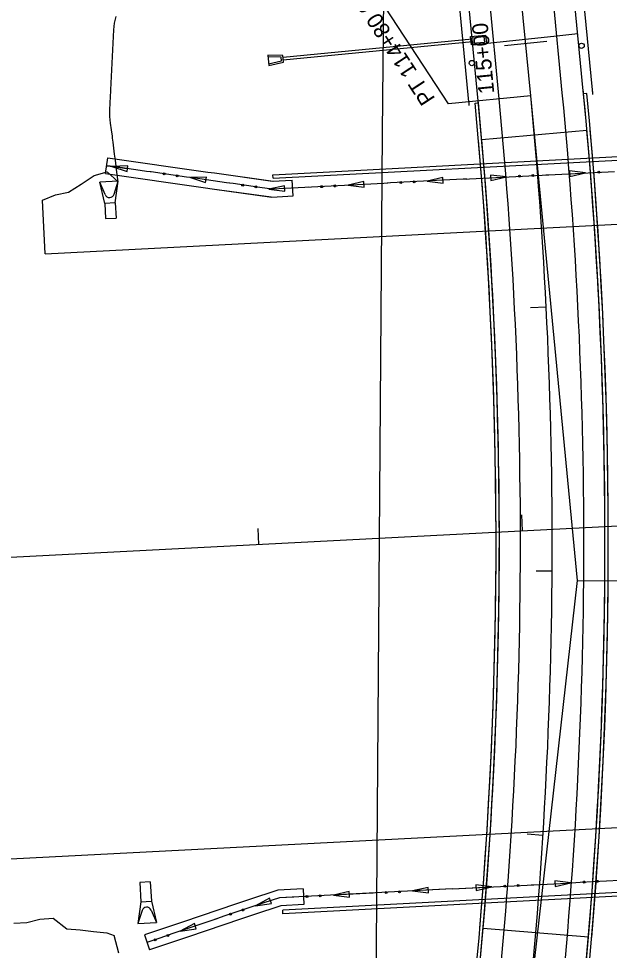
# Model space of a CAD drawing. Extents: x 1311167 to 1314552, y 2087587 to 2090602.
# Drawn here: x 1313861.6 to 1314085.4, y 2089153.5 to 2089506 of the extents above; entities that cross this region are included whole.
import ezdxf

# ---------------------------------------------------------------- set-up
doc = ezdxf.new("R2010")
doc.units = 0
for name, color, linetype in [('MOT_Proposed Road_1A', 7, 'Continuous'), ('MOT_Proposed Road_2', 7, 'Continuous'), ('R_Bridge', 7, 'Continuous'), ('R_Guardrail', 7, 'Continuous'), ('R_Horz Alg Annot_Side Road', 7, 'Continuous'), ('R_Horz Alg Stationing', 7, 'Continuous'), ('R_Proposed Road', 7, 'Continuous'), ('R_Shoulder', 7, 'Continuous'), ('R_Special Ditch', 7, 'Continuous'), ('S_DITCHLINE', 7, 'Continuous'), ('S_EDGE_BITUMINOUS', 7, 'Continuous'), ('S_EDGE_CONCRETE', 7, 'Continuous'), ('S_EDGE_PAVEMENT', 7, 'Continuous'), ('S_PAVEMENT_CROWN', 7, 'Continuous'), ('S_WALL', 7, 'Continuous')]:
    doc.layers.add(name, color=color, linetype=linetype)

msp = doc.modelspace()

# ---------------------------------------------------------------- linework, layer by layer
at = {"layer": 'MOT_Proposed Road_1A'}
for p, q in [((1313894.56, 2089447.41), (1313895.4, 2089453.35)), ((1313957.76, 2089444.53), (1313965.27, 2089444.92)), ((1313965.59, 2089438.93), (1313965.27, 2089444.92)), ((1313957.5, 2089438.51), (1313965.59, 2089438.93)), ((1313969.36, 2089176.77), (1313969.68, 2089170.78)), ((1313909.25, 2089159.3), (1313911.18, 2089153.61))]:
    msp.add_line(p, q, dxfattribs=at)
for points in [[(1313895.4, 2089453.35), (1313933.23, 2089447.99), (1313935.75, 2089447.64), (1313957.76, 2089444.53)], [(1313895.4, 2089453.35), (1313933.23, 2089447.99), (1313935.75, 2089447.64), (1313958.05, 2089444.49)], [(1313894.56, 2089447.41), (1313932.39, 2089442.05), (1313934.91, 2089441.69), (1313957.5, 2089438.51)], [(1313894.56, 2089447.41), (1313932.39, 2089442.05), (1313934.91, 2089441.69), (1313957.21, 2089438.55)], [(1313969.36, 2089176.77), (1313959.83, 2089176.28), (1313948.64, 2089172.62), (1313943.7, 2089170.97), (1313924.01, 2089164.29), (1313919.09, 2089162.62), (1313909.25, 2089159.3)], [(1313969.68, 2089170.78), (1313960.94, 2089170.33), (1313950.52, 2089166.92), (1313945.61, 2089165.28), (1313925.94, 2089158.61), (1313921.02, 2089156.94), (1313911.18, 2089153.61)]]:
    msp.add_lwpolyline(points, dxfattribs=at)
at = {"layer": 'MOT_Proposed Road_2'}
for p, q in [((1314075.48, 2089478.75), (1314071.45, 2089520.56)), ((1314035.66, 2089474.91), (1314031.6, 2089517.08))]:
    msp.add_line(p, q, dxfattribs=at)
for centre in [(1314074.84, 2089495.76), (1314033.28, 2089489.21)]:
    msp.add_circle(centre, 1, dxfattribs=at)
for radius, start in [(1782.95, 5.44344), (1742.95, 5.45487)]:
    msp.add_arc((1312300.74, 2089307.86), radius, start, 5.5, dxfattribs=at)
at = {"layer": 'R_Bridge'}
for points in [[(1314045.69, 2089495.92), (1314061.62, 2089497.45)], [(1314055.44, 2089396.7), (1314061.43, 2089397)], [(1314057.65, 2089297.08), (1314063.65, 2089297.04)], [(1314054.21, 2089197.49), (1314060.2, 2089197.11)]]:
    msp.add_lwpolyline(points, dxfattribs=at)
at = {"layer": 'R_Guardrail'}
msp.add_line((1314024.38, 2089473.82), (1313981.59, 2089539.33), dxfattribs=at)
for points in [[(1314055.57, 2089476.83), (1314024.38, 2089473.82)], [(1314052.57, 2089110.2), (1314073.23, 2089293.36), (1314055.57, 2089476.83)], [(1314073.23, 2089293.36), (1314193.23, 2089292.37)]]:
    msp.add_lwpolyline(points, dxfattribs=at)
at = {"layer": 'R_Horz Alg Annot_Side Road'}
for p, q in [((1314078.96, 2089479.08), (1314074.93, 2089520.9)), ((1314032.18, 2089474.58), (1314028.12, 2089516.74))]:
    msp.add_line(p, q, dxfattribs=at)
for radius, start in [(1786.45, 5.44344), (1739.45, 5.45487)]:
    msp.add_arc((1312300.74, 2089307.86), radius, start, 5.5, dxfattribs=at)
at = {"layer": 'R_Horz Alg Stationing'}
for p, q in [((1313999.49, 2089462.84), (1314005.79, 2090288.55)), ((1313997.14, 2089155.24), (1313999.49, 2089462.84)), ((1313988.32, 2088000.7), (1313997.14, 2089155.24))]:
    msp.add_line(p, q, dxfattribs=at)
at = {"layer": 'R_Proposed Road'}
for p, q in [((1314055.57, 2089476.83), (1314011.87, 2089930.69)), ((1314055.57, 2089476.83), (1314011.87, 2089930.69)), ((1313503.08, 2089283.78), (1314551.67, 2089338.12))]:
    msp.add_line(p, q, dxfattribs=at)
msp.add_arc((1312300.74, 2089307.86), 1762.95, 353.5625, 5.5, dxfattribs=at)
msp.add_arc((1312300.74, 2089307.86), 1762.95, 353.5625, 5.5, dxfattribs=at)
at = {"layer": 'R_Shoulder'}
for points in [[(1314052.03, 2089318.24), (1314052.34, 2089312.25)], [(1313952.17, 2089313.06), (1313952.48, 2089307.07)]]:
    msp.add_lwpolyline(points, dxfattribs=at)
at = {"layer": 'R_Special Ditch'}
for p, q in [((1314076.83, 2089477.72), (1314075.59, 2089477.6)), ((1314034.49, 2089474.01), (1314035.74, 2089474.13)), ((1314076.86, 2089463.66), (1314037.01, 2089460.19)), ((1314077.41, 2089158.47), (1314037.55, 2089161.79))]:
    msp.add_line(p, q, dxfattribs=at)
for radius, start, end in [(1782.95, 354.7437, 5.46314), (1784.2, 354.74371, 5.46313), (1742.95, 354.73258, 5.47426), (1741.7, 354.73258, 5.47425), (1782.95, 355.19361, 5.01323), (1784.2, 355.19363, 5.01321), (1741.7, 355.19278, 5.01406), (1742.95, 355.19281, 5.01403)]:
    msp.add_arc((1312300.74, 2089307.86), radius, start, end, dxfattribs=at)
at = {"layer": 'S_DITCHLINE'}
for p, q in [((1313903.01, 2089450.31), (1313896.92, 2089450.11)), ((1313896.92, 2089450.11), (1313902.71, 2089448.22)), ((1313902.71, 2089448.22), (1313903.01, 2089450.31)), ((1313932.75, 2089446.1), (1313926.66, 2089445.89)), ((1313926.66, 2089445.89), (1313932.45, 2089444)), ((1313932.45, 2089444), (1313932.75, 2089446.1)), ((1314022.32, 2089445.93), (1314016.39, 2089444.56)), ((1314022.43, 2089443.82), (1314022.32, 2089445.93)), ((1314046.35, 2089446.12), (1314040.3, 2089446.86)), ((1314040.3, 2089446.86), (1314040.41, 2089444.75)), ((1314046.35, 2089446.12), (1314040.3, 2089446.86)), ((1314040.3, 2089446.86), (1314040.41, 2089444.75)), ((1314040.41, 2089444.75), (1314046.35, 2089446.12)), ((1314040.41, 2089444.75), (1314046.35, 2089446.12)), ((1314076.34, 2089447.67), (1314070.3, 2089448.42)), ((1314070.3, 2089448.42), (1314070.41, 2089446.3)), ((1314076.34, 2089447.67), (1314070.3, 2089448.42)), ((1314070.3, 2089448.42), (1314070.41, 2089446.3)), ((1314070.41, 2089446.3), (1314076.34, 2089447.67)), ((1314070.41, 2089446.3), (1314076.34, 2089447.67)), ((1313962.33, 2089442.82), (1313956.39, 2089441.45)), ((1313962.44, 2089440.71), (1313962.33, 2089442.82)), ((1313992.33, 2089444.38), (1313986.39, 2089443.01)), ((1313986.39, 2089443.01), (1313992.44, 2089442.26)), ((1313992.44, 2089442.26), (1313992.33, 2089444.38)), ((1314016.39, 2089444.56), (1314022.43, 2089443.82)), ((1313956.39, 2089441.45), (1313962.44, 2089440.71)), ((1314040.8, 2089177.47), (1314034.76, 2089178.22)), ((1314034.76, 2089178.22), (1314034.86, 2089176.1)), ((1314070.8, 2089179.02), (1314064.75, 2089179.77)), ((1314064.75, 2089179.77), (1314064.86, 2089177.66)), ((1314064.86, 2089177.66), (1314070.8, 2089179.02)), ((1314025.82, 2089176.69), (1313960.38, 2089173.3)), ((1313986.78, 2089175.73), (1313980.84, 2089174.36)), ((1313986.89, 2089173.62), (1313986.78, 2089175.73)), ((1314016.78, 2089177.28), (1314010.84, 2089175.92)), ((1314010.84, 2089175.92), (1314016.89, 2089175.17)), ((1314016.89, 2089175.17), (1314016.78, 2089177.28)), ((1314034.86, 2089176.1), (1314040.8, 2089177.47)), ((1313956.68, 2089173.2), (1313951.31, 2089170.33)), ((1313951.31, 2089170.33), (1313957.34, 2089171.19)), ((1313957.34, 2089171.19), (1313956.68, 2089173.2)), ((1313980.84, 2089174.36), (1313986.89, 2089173.62)), ((1313928.19, 2089163.66), (1313922.85, 2089160.73)), ((1313922.85, 2089160.73), (1313928.87, 2089161.65)), ((1313928.87, 2089161.65), (1313928.19, 2089163.66))]:
    msp.add_line(p, q, dxfattribs=at)
for points in [[(1313894.98, 2089450.38), (1313897.5, 2089450.02), (1313900.03, 2089449.67), (1313902.55, 2089449.31)], [(1313957.63, 2089441.52), (1313952.98, 2089442.17), (1313950.46, 2089442.53), (1313947.94, 2089442.89), (1313945.42, 2089443.24), (1313942.9, 2089443.6), (1313940.38, 2089443.95), (1313937.85, 2089444.31), (1313935.33, 2089444.67), (1313932.81, 2089445.02), (1313930.29, 2089445.38), (1313927.77, 2089445.74), (1313925.24, 2089446.09), (1313922.72, 2089446.45), (1313920.2, 2089446.81), (1313917.68, 2089447.17), (1313915.16, 2089447.52), (1313912.64, 2089447.88), (1313910.11, 2089448.24), (1313907.59, 2089448.6), (1313905.07, 2089448.95), (1313902.55, 2089449.31), (1313900.03, 2089449.67), (1313897.5, 2089450.02), (1313894.98, 2089450.38)], [(1313911.77, 2089448), (1313910.11, 2089448.24), (1313907.59, 2089448.6), (1313905.07, 2089448.95), (1313902.55, 2089449.31), (1313900.03, 2089449.67), (1313897.5, 2089450.02), (1313896.92, 2089450.11)], [(1313911.81, 2089448), (1313911.77, 2089448)], [(1313941.51, 2089443.79), (1313940.38, 2089443.95), (1313937.85, 2089444.31), (1313935.33, 2089444.67), (1313932.81, 2089445.02), (1313930.29, 2089445.38), (1313927.77, 2089445.74), (1313926.66, 2089445.89)], [(1314031.37, 2089445.34), (1314032.42, 2089445.39), (1314034.92, 2089445.52), (1314037.42, 2089445.65), (1314039.91, 2089445.78), (1314042.41, 2089445.91), (1314044.91, 2089446.04), (1314047.4, 2089446.17), (1314049.9, 2089446.3), (1314052.4, 2089446.43), (1314054.89, 2089446.56), (1314057.39, 2089446.69), (1314059.89, 2089446.82), (1314062.38, 2089446.95), (1314064.88, 2089447.08), (1314067.38, 2089447.21), (1314069.87, 2089447.34), (1314072.37, 2089447.46), (1314074.87, 2089447.59), (1314077.36, 2089447.72), (1314079.86, 2089447.85), (1314082.36, 2089447.98), (1314084.85, 2089448.11), (1314087.35, 2089448.24)], [(1314031.37, 2089445.34), (1314032.42, 2089445.39), (1314034.92, 2089445.52), (1314037.42, 2089445.65), (1314039.91, 2089445.78), (1314042.41, 2089445.91), (1314044.91, 2089446.04), (1314046.35, 2089446.12)], [(1314031.37, 2089445.34), (1314032.42, 2089445.39), (1314034.92, 2089445.52), (1314037.42, 2089445.65), (1314039.91, 2089445.78), (1314042.41, 2089445.91), (1314044.91, 2089446.04), (1314046.35, 2089446.12)], [(1314061.33, 2089446.89), (1314061.36, 2089446.89)], [(1314061.33, 2089446.89), (1314061.36, 2089446.89)], [(1314061.36, 2089446.89), (1314062.38, 2089446.95), (1314064.88, 2089447.08), (1314067.38, 2089447.21), (1314069.87, 2089447.34), (1314072.37, 2089447.46), (1314074.87, 2089447.59), (1314076.34, 2089447.67)], [(1314061.36, 2089446.89), (1314062.38, 2089446.95), (1314064.88, 2089447.08), (1314067.38, 2089447.21), (1314069.87, 2089447.34), (1314072.37, 2089447.46), (1314074.87, 2089447.59), (1314076.34, 2089447.67)], [(1313941.55, 2089443.79), (1313941.51, 2089443.79)], [(1314031.37, 2089445.34), (1314029.93, 2089445.27), (1314027.43, 2089445.14), (1314024.93, 2089445.01), (1314022.44, 2089444.88), (1314019.94, 2089444.75), (1314017.44, 2089444.62), (1314014.95, 2089444.49), (1314012.45, 2089444.36), (1314009.95, 2089444.23), (1314007.46, 2089444.1), (1314004.96, 2089443.97), (1314002.46, 2089443.84), (1313999.97, 2089443.71), (1313997.47, 2089443.58), (1313994.97, 2089443.45), (1313992.48, 2089443.32), (1313989.98, 2089443.2), (1313987.48, 2089443.07), (1313984.99, 2089442.94), (1313982.49, 2089442.81), (1313979.99, 2089442.68), (1313977.5, 2089442.55), (1313975, 2089442.42), (1313972.5, 2089442.29), (1313970.01, 2089442.16), (1313967.51, 2089442.03), (1313965.01, 2089441.9), (1313962.52, 2089441.77), (1313957.63, 2089441.52)], [(1314001.37, 2089443.79), (1313999.97, 2089443.71), (1313997.47, 2089443.58), (1313994.97, 2089443.45), (1313992.48, 2089443.32), (1313989.98, 2089443.2), (1313987.48, 2089443.07), (1313986.39, 2089443.01)], [(1314001.41, 2089443.79), (1314001.37, 2089443.79)], [(1314031.37, 2089445.34), (1314029.93, 2089445.27), (1314027.43, 2089445.14), (1314024.93, 2089445.01), (1314022.44, 2089444.88), (1314019.94, 2089444.75), (1314017.44, 2089444.62), (1314016.39, 2089444.56)], [(1313971.37, 2089442.23), (1313970.01, 2089442.16), (1313967.51, 2089442.03), (1313965.01, 2089441.9), (1313962.52, 2089441.77), (1313957.63, 2089441.52), (1313956.4, 2089441.69)], [(1313971.41, 2089442.23), (1313971.37, 2089442.23)], [(1314025.82, 2089176.69), (1314049.29, 2089177.91), (1314054.28, 2089178.17), (1314059.28, 2089178.43), (1314064.27, 2089178.69), (1314069.26, 2089178.94), (1314074.26, 2089179.2), (1314079.25, 2089179.46), (1314084.24, 2089179.72), (1314089.24, 2089179.98)], [(1314055.78, 2089178.25), (1314055.82, 2089178.25)], [(1314055.82, 2089178.25), (1314059.28, 2089178.43), (1314064.27, 2089178.69), (1314069.26, 2089178.94), (1314070.8, 2089179.02)], [(1313995.82, 2089175.14), (1313980.84, 2089174.36)], [(1313995.86, 2089175.14), (1313995.82, 2089175.14)], [(1314025.82, 2089176.69), (1314010.84, 2089175.92)], [(1314025.82, 2089176.69), (1314040.8, 2089177.47)], [(1313960.38, 2089173.3), (1313954.5, 2089171.38), (1313949.58, 2089169.77), (1313944.66, 2089168.13), (1313939.74, 2089166.46), (1313934.82, 2089164.79), (1313929.9, 2089163.12), (1313924.98, 2089161.45), (1313920.06, 2089159.78), (1313915.14, 2089158.12), (1313910.21, 2089156.46)], [(1313965.83, 2089173.58), (1313960.38, 2089173.3), (1313954.5, 2089171.38), (1313951.31, 2089170.33)], [(1313965.86, 2089173.59), (1313965.83, 2089173.58)], [(1313937.05, 2089165.55), (1313934.82, 2089164.79), (1313929.9, 2089163.12), (1313924.98, 2089161.45), (1313922.85, 2089160.73)], [(1313937.09, 2089165.56), (1313937.05, 2089165.55)]]:
    msp.add_lwpolyline(points, dxfattribs=at)
for centre in [(1313916.74, 2089447.26), (1313921.7, 2089446.56), (1314051.34, 2089446.41), (1314051.34, 2089446.41), (1314056.35, 2089446.67), (1314056.35, 2089446.67), (1314081.34, 2089447.97), (1314081.34, 2089447.97), (1313946.48, 2089443.06), (1313951.44, 2089442.36), (1313976.39, 2089442.45), (1313981.39, 2089442.71), (1314006.39, 2089444.01), (1314011.39, 2089444.27), (1314045.8, 2089177.76), (1314050.8, 2089178.02), (1314075.8, 2089179.32), (1314080.8, 2089179.58), (1313975.85, 2089174.07), (1314000.84, 2089175.36), (1314005.84, 2089175.62), (1313970.84, 2089173.81), (1313941.82, 2089167.12), (1313946.57, 2089168.73), (1313913.37, 2089157.48), (1313918.12, 2089159.09)]:
    msp.add_circle(centre, 0.375, dxfattribs=at)
at = {"layer": 'S_EDGE_BITUMINOUS'}
for p, q in [((1314033.42, 2089498.21), (1313961.75, 2089491.31)), ((1314033.51, 2089497.21), (1313961.84, 2089490.31)), ((1313955.97, 2089492.25), (1313956.35, 2089488.27)), ((1313961.68, 2089492.04), (1313955.97, 2089492.25)), ((1313961.92, 2089489.55), (1313961.68, 2089492.04)), ((1313956.35, 2089488.27), (1313961.92, 2089489.55)), ((1313899.33, 2089444.51), (1313892.34, 2089444.16)), ((1313894.25, 2089436.07), (1313892.34, 2089444.16)), ((1313894.36, 2089439.44), (1313892.34, 2089444.16)), ((1313897.8, 2089439.61), (1313899.33, 2089444.51)), ((1313898.24, 2089436.27), (1313899.33, 2089444.51)), ((1313898.24, 2089436.27), (1313894.25, 2089436.07)), ((1313894.25, 2089436.07), (1313894.54, 2089430.38)), ((1313898.24, 2089436.27), (1313898.53, 2089430.58)), ((1313894.54, 2089430.38), (1313898.53, 2089430.58)), ((1313911.49, 2089179.39), (1313907.49, 2089179.17)), ((1313907.49, 2089179.17), (1313907.91, 2089171.86)), ((1313911.49, 2089179.39), (1313911.9, 2089172.08)), ((1313907.91, 2089171.88), (1313906.83, 2089163.64)), ((1313907.91, 2089171.88), (1313911.9, 2089172.08)), ((1313911.9, 2089172.08), (1313913.82, 2089164)), ((1313908.36, 2089168.54), (1313906.83, 2089163.64)), ((1313911.79, 2089168.71), (1313913.82, 2089164)), ((1313906.83, 2089163.64), (1313913.82, 2089164))]:
    msp.add_line(p, q, dxfattribs=at)
for points in [[(1314033.12, 2089496.06), (1314032.81, 2089499.27), (1314038.45, 2089499.81), (1314038.76, 2089496.6)], [(1314033.57, 2089496.6), (1314033.36, 2089498.82), (1314037.84, 2089499.25), (1314038.05, 2089497.03)]]:
    msp.add_lwpolyline(points, close=True, dxfattribs=at)
msp.add_lwpolyline([(1313956.28, 2089488.93), (1313961.2, 2089490.07), (1313961.07, 2089491.4), (1313956.03, 2089491.58)], dxfattribs=at)
for centre, start, end in [((1313896.05, 2089440.17), 203.1994, 342.5622), ((1313910.11, 2089167.99), 23.2852, 162.648)]:
    msp.add_arc(centre, 1.83, start, end, dxfattribs=at)
at = {"layer": 'S_EDGE_CONCRETE'}
for points in [[(1313899.35, 2089444.29), (1313898.87, 2089447.98), (1313898.58, 2089450.24), (1313898.28, 2089452.5), (1313897.99, 2089454.76), (1313897.7, 2089457.01), (1313897.41, 2089459.27), (1313897.2, 2089460.86), (1313897.11, 2089461.53), (1313896.79, 2089464), (1313896.47, 2089466.48), (1313896.15, 2089468.96), (1313896.2, 2089471.48), (1313896.33, 2089474), (1313896.45, 2089476.53), (1313896.55, 2089478.61), (1313896.57, 2089479.05), (1313896.7, 2089481.57), (1313896.82, 2089484.1), (1313896.94, 2089486.62), (1313897.07, 2089489.14), (1313897.19, 2089491.67), (1313897.31, 2089494.19), (1313897.44, 2089496.71), (1313897.56, 2089499.24), (1313897.68, 2089501.76), (1313897.92, 2089504.3), (1313898.52, 2089506.87)], [(1313871.68, 2089417.04), (1313870.62, 2089437.36), (1313875.53, 2089439.32), (1313880.48, 2089440.42), (1313885.33, 2089443.34), (1313890.17, 2089446.7), (1313895.11, 2089448), (1313899.35, 2089444.29)], [(1313859.77, 2089163.75), (1313864.77, 2089163.96), (1313869.7, 2089165.32), (1313874.69, 2089165.63), (1313879.91, 2089161.57), (1313884.94, 2089161.18), (1313889.97, 2089160.62), (1313895.01, 2089160.09), (1313897.83, 2089159.07)], [(1313899.63, 2089152.45), (1313897.83, 2089159.07)]]:
    msp.add_lwpolyline(points, dxfattribs=at)
at = {"layer": 'S_EDGE_PAVEMENT'}
for p, q in [((1314075.48, 2089478.75), (1314031.77, 2089932.6)), ((1314035.66, 2089474.91), (1313991.96, 2089928.77)), ((1313871.68, 2089417.04), (1314480.86, 2089448.61)), ((1313553.62, 2089172.25), (1314203.05, 2089205.9))]:
    msp.add_line(p, q, dxfattribs=at)
for radius in [1782.95, 1742.95]:
    msp.add_arc((1312300.74, 2089307.86), radius, 353.5625, 5.5, dxfattribs=at)
at = {"layer": 'S_PAVEMENT_CROWN'}
for p, q in [((1314043.62, 2089475.68), (1313999.92, 2089929.54)), ((1314067.51, 2089477.98), (1314023.81, 2089931.84)), ((1314041.57, 2089496.97), (1314065.43, 2089499.56)), ((1314065.43, 2089499.56), (1314073.39, 2089500.42)), ((1314033.62, 2089496.1), (1314041.57, 2089496.97))]:
    msp.add_line(p, q, dxfattribs=at)
for radius in [1774.95, 1774.95, 1750.95, 1750.95]:
    msp.add_arc((1312300.74, 2089307.86), radius, 353.5625, 5.5, dxfattribs=at)
at = {"layer": 'S_WALL'}
for p, q in [((1313957.93, 2089446.98), (1314164.64, 2089457.82)), ((1313958, 2089445.64), (1314164.71, 2089456.49)), ((1313958, 2089445.64), (1313957.93, 2089446.98)), ((1314167.86, 2089179.49), (1313961.65, 2089168.61)), ((1314167.93, 2089178.15), (1313961.72, 2089167.28)), ((1313961.72, 2089167.28), (1313961.65, 2089168.61))]:
    msp.add_line(p, q, dxfattribs=at)

# ---------------------------------------------------------------- texts
at = {"layer": 'R_Bridge'}
msp.add_text('115+00', height=6, rotation=95.5, dxfattribs=at).set_placement((1314041.79, 2089477.82))
at = {"layer": 'R_Guardrail'}
msp.add_text('PT 114+80.05', height=6, rotation=123.1515, dxfattribs=at).set_placement((1314019.54, 2089475.75))

doc.saveas('drawing.dxf')
